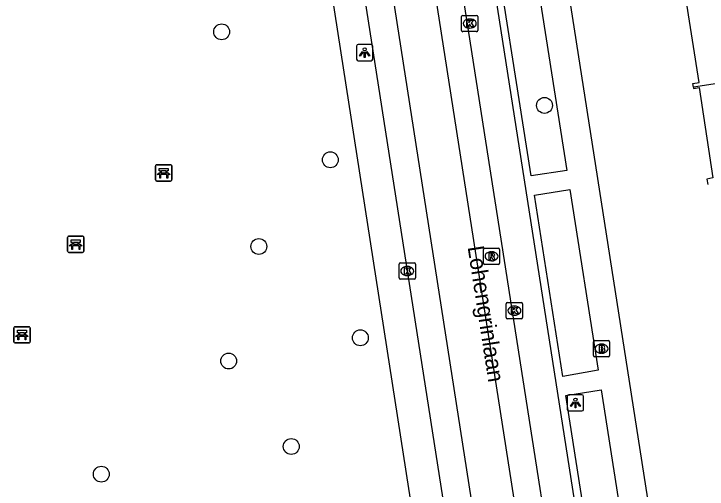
# Model space of a CAD drawing. Extents: x 160077 to 160945, y 386481 to 387498.
# Drawn here: x 160634.83 to 160677.56, y 386939.33 to 386968.61 of the extents above; entities that cross this region are included whole.
import ezdxf

# ---------------------------------------------------------------- set-up
doc = ezdxf.new("R2010")
doc.units = 0
for name, color, linetype in [('IMGEO_Bank', 7, 'Continuous'), ('IMGEO_Boom', 7, 'Continuous'), ('IMGEO_Brandkraan', 7, 'Continuous'), ('IMGEO_Kolk', 7, 'Continuous'), ('IMGEO_Lichtpunt', 7, 'Continuous'), ('IMGEO_Openbare_ruimte_label', 7, 'Continuous'), ('IMGEO_Pand', 7, 'Continuous'), ('IMGEO_Rijbaan_lokaal_gesloten', 7, 'Continuous'), ('IMGEO_Rioolput', 7, 'Continuous'), ('IMGEO_Voetpad_open', 7, 'Continuous')]:
    doc.layers.add(name, color=color, linetype=linetype)

msp = doc.modelspace()

# ---------------------------------------------------------------- linework, layer by layer
at = {"layer": 'IMGEO_Bank'}
for p, q in [((160643.636, 386959.313), (160644.477, 386959.313)), ((160644.477, 386959.313), (160643.636, 386959.313)), ((160643.561, 386958.388), (160643.561, 386959.229)), ((160643.561, 386959.229), (160643.561, 386958.388)), ((160643.87, 386958.819), (160643.87, 386958.925)), ((160643.914, 386958.925), (160643.914, 386958.819)), ((160644.202, 386958.931), (160643.92, 386958.931)), ((160644.208, 386958.819), (160644.208, 386958.925)), ((160644.252, 386958.925), (160644.252, 386958.819)), ((160644.561, 386959.238), (160644.561, 386958.397)), ((160644.561, 386958.397), (160644.561, 386959.238)), ((160644.258, 386958.711), (160643.865, 386958.711)), ((160643.92, 386958.813), (160644.202, 386958.813)), ((160644.486, 386958.313), (160643.645, 386958.313)), ((160643.645, 386958.313), (160644.486, 386958.313)), ((160638.139, 386953.992), (160638.139, 386954.833)), ((160638.139, 386954.833), (160638.139, 386953.992)), ((160638.214, 386954.917), (160639.055, 386954.917)), ((160639.055, 386954.917), (160638.214, 386954.917)), ((160639.139, 386954.842), (160639.139, 386954.001)), ((160639.139, 386954.001), (160639.139, 386954.842)), ((160638.836, 386954.315), (160638.443, 386954.315)), ((160638.448, 386954.423), (160638.448, 386954.529)), ((160638.492, 386954.529), (160638.492, 386954.423)), ((160638.78, 386954.535), (160638.498, 386954.535)), ((160638.498, 386954.417), (160638.78, 386954.417)), ((160638.786, 386954.423), (160638.786, 386954.529)), ((160638.83, 386954.529), (160638.83, 386954.423)), ((160639.064, 386953.917), (160638.223, 386953.917)), ((160638.223, 386953.917), (160639.064, 386953.917)), ((160634.825, 386948.415), (160634.825, 386949.256)), ((160634.825, 386949.256), (160634.825, 386948.415)), ((160634.9, 386949.34), (160635.741, 386949.34)), ((160635.741, 386949.34), (160634.9, 386949.34)), ((160635.825, 386949.265), (160635.825, 386948.424)), ((160635.825, 386948.424), (160635.825, 386949.265)), ((160635.522, 386948.738), (160635.129, 386948.738)), ((160635.134, 386948.846), (160635.134, 386948.952)), ((160635.178, 386948.952), (160635.178, 386948.846)), ((160635.466, 386948.958), (160635.184, 386948.958)), ((160635.184, 386948.84), (160635.466, 386948.84)), ((160635.472, 386948.846), (160635.472, 386948.952)), ((160635.516, 386948.952), (160635.516, 386948.846)), ((160635.75, 386948.34), (160634.909, 386948.34)), ((160634.909, 386948.34), (160635.75, 386948.34))]:
    msp.add_line(p, q, dxfattribs=at)
for points in [[(160643.864, 386958.931), (160643.778, 386958.931), (160643.778, 386959.092), (160644.341, 386959.092), (160644.341, 386958.931), (160644.258, 386958.931)], [(160643.808, 386958.711), (160643.666, 386958.711), (160643.778, 386958.813), (160643.864, 386958.813)], [(160643.858, 386958.704), (160643.858, 386958.497), (160643.815, 386958.497), (160643.815, 386958.704)], [(160644.258, 386958.813), (160644.341, 386958.813), (160644.453, 386958.711), (160644.314, 386958.711)], [(160644.308, 386958.704), (160644.308, 386958.497), (160644.264, 386958.497), (160644.264, 386958.704)], [(160638.442, 386954.535), (160638.356, 386954.535), (160638.356, 386954.696), (160638.919, 386954.696), (160638.919, 386954.535), (160638.836, 386954.535)], [(160638.386, 386954.315), (160638.244, 386954.315), (160638.356, 386954.417), (160638.442, 386954.417)], [(160638.436, 386954.308), (160638.436, 386954.101), (160638.393, 386954.101), (160638.393, 386954.308)], [(160638.836, 386954.417), (160638.919, 386954.417), (160639.031, 386954.315), (160638.892, 386954.315)], [(160638.886, 386954.308), (160638.886, 386954.101), (160638.842, 386954.101), (160638.842, 386954.308)], [(160635.128, 386948.958), (160635.042, 386948.958), (160635.042, 386949.119), (160635.605, 386949.119), (160635.605, 386948.958), (160635.522, 386948.958)], [(160635.072, 386948.738), (160634.93, 386948.738), (160635.042, 386948.84), (160635.128, 386948.84)], [(160635.122, 386948.731), (160635.122, 386948.524), (160635.079, 386948.524), (160635.079, 386948.731)], [(160635.522, 386948.84), (160635.605, 386948.84), (160635.717, 386948.738), (160635.578, 386948.738)], [(160635.572, 386948.731), (160635.572, 386948.524), (160635.528, 386948.524), (160635.528, 386948.731)]]:
    msp.add_lwpolyline(points, dxfattribs=at)
for centre, radius, start, end in [((160643.639, 386959.235), 0.0779, 92.4484, 184.2845), ((160643.639, 386959.235), 0.0779, 92.4484, 184.2845), ((160644.483, 386959.235), 0.0779, 2.4484, 94.2845), ((160644.483, 386959.235), 0.0779, 2.4484, 94.2845), ((160643.863, 386958.924), 0.00671, 2.8957, 87.1043), ((160643.92, 386958.924), 0.00671, 92.8957, 177.1043), ((160644.202, 386958.924), 0.00671, 2.8957, 87.1043), ((160644.259, 386958.924), 0.00671, 92.8957, 177.1043), ((160643.808, 386958.704), 0.00671, 2.8957, 87.1043), ((160643.865, 386958.704), 0.00671, 92.8957, 177.1043), ((160643.863, 386958.82), 0.00671, 272.8957, 357.1043), ((160643.92, 386958.82), 0.00671, 182.8957, 267.1043), ((160644.202, 386958.82), 0.00671, 272.8957, 357.1043), ((160644.259, 386958.82), 0.00671, 182.8957, 267.1043), ((160644.257, 386958.704), 0.00671, 2.8957, 87.1043), ((160644.314, 386958.704), 0.00671, 92.8957, 177.1043), ((160643.639, 386958.391), 0.0779, 182.4484, 274.2845), ((160643.639, 386958.391), 0.0779, 182.4484, 274.2845), ((160644.483, 386958.391), 0.0779, 272.4484, 4.2845), ((160644.483, 386958.391), 0.0779, 272.4484, 4.2845), ((160638.217, 386954.839), 0.0779, 92.4484, 184.2845), ((160638.217, 386954.839), 0.0779, 92.4484, 184.2845), ((160639.061, 386954.839), 0.0779, 2.4484, 94.2845), ((160639.061, 386954.839), 0.0779, 2.4484, 94.2845), ((160638.386, 386954.308), 0.00671, 2.8957, 87.1043), ((160638.443, 386954.308), 0.00671, 92.8957, 177.1043), ((160638.441, 386954.528), 0.00671, 2.8957, 87.1043), ((160638.441, 386954.424), 0.00671, 272.8957, 357.1043), ((160638.498, 386954.528), 0.00671, 92.8957, 177.1043), ((160638.498, 386954.424), 0.00671, 182.8957, 267.1043), ((160638.78, 386954.528), 0.00671, 2.8957, 87.1043), ((160638.78, 386954.424), 0.00671, 272.8957, 357.1043), ((160638.837, 386954.528), 0.00671, 92.8957, 177.1043), ((160638.837, 386954.424), 0.00671, 182.8957, 267.1043), ((160638.835, 386954.308), 0.00671, 2.8957, 87.1043), ((160638.892, 386954.308), 0.00671, 92.8957, 177.1043), ((160638.217, 386953.995), 0.0779, 182.4484, 274.2845), ((160638.217, 386953.995), 0.0779, 182.4484, 274.2845), ((160639.061, 386953.995), 0.0779, 272.4484, 4.2845), ((160639.061, 386953.995), 0.0779, 272.4484, 4.2845), ((160634.903, 386949.262), 0.0779, 92.4484, 184.2845), ((160634.903, 386949.262), 0.0779, 92.4484, 184.2845), ((160635.747, 386949.262), 0.0779, 2.4484, 94.2845), ((160635.747, 386949.262), 0.0779, 2.4484, 94.2845), ((160635.072, 386948.731), 0.00671, 2.8957, 87.1043), ((160635.129, 386948.731), 0.00671, 92.8957, 177.1043), ((160635.127, 386948.951), 0.00671, 2.8957, 87.1043), ((160635.127, 386948.847), 0.00671, 272.8957, 357.1043), ((160635.184, 386948.951), 0.00671, 92.8957, 177.1043), ((160635.184, 386948.847), 0.00671, 182.8957, 267.1043), ((160635.466, 386948.951), 0.00671, 2.8957, 87.1043), ((160635.466, 386948.847), 0.00671, 272.8957, 357.1043), ((160635.523, 386948.951), 0.00671, 92.8957, 177.1043), ((160635.523, 386948.847), 0.00671, 182.8957, 267.1043), ((160635.521, 386948.731), 0.00671, 2.8957, 87.1043), ((160635.578, 386948.731), 0.00671, 92.8957, 177.1043), ((160634.903, 386948.418), 0.0779, 182.4484, 274.2845), ((160634.903, 386948.418), 0.0779, 182.4484, 274.2845), ((160635.747, 386948.418), 0.0779, 272.4484, 4.2845), ((160635.747, 386948.418), 0.0779, 272.4484, 4.2845)]:
    msp.add_arc(centre, radius, start, end, dxfattribs=at)
at = {"layer": 'IMGEO_Boom'}
for centre in [(160647.634, 386967.504), (160667.541, 386962.97), (160654.334, 386959.621), (160649.927, 386954.28), (160656.186, 386948.656), (160648.068, 386947.222), (160651.925, 386941.956), (160640.215, 386940.252)]:
    msp.add_circle(centre, 0.489, dxfattribs=at)
at = {"layer": 'IMGEO_Brandkraan'}
for p, q in [((160670.553, 386947.56), (160670.553, 386948.412)), ((160670.628, 386948.486), (160671.48, 386948.486)), ((160671.041, 386948.266), (160671.066, 386948.266)), ((160671.554, 386948.412), (160671.554, 386947.56)), ((160671.48, 386947.486), (160670.628, 386947.486)), ((160671.064, 386947.706), (160671.039, 386947.706))]:
    msp.add_line(p, q, dxfattribs=at)
for points in [[(160670.553, 386947.56), (160670.553, 386948.412)], [(160670.628, 386948.486), (160671.48, 386948.486)], [(160670.901, 386948.186), (160670.901, 386947.786), (160671.114, 386947.786)], [(160671.132, 386948.186), (160670.901, 386948.186)], [(160671.554, 386948.412), (160671.554, 386947.56)], [(160671.08, 386948.105), (160671.026, 386948.105), (160671.026, 386948.029)], [(160671.026, 386948.029), (160671.079, 386948.029)], [(160671.088, 386947.953), (160671.026, 386947.953), (160671.026, 386947.872)], [(160671.026, 386947.872), (160671.088, 386947.872)], [(160671.48, 386947.486), (160670.628, 386947.486)]]:
    msp.add_lwpolyline(points, dxfattribs=at)
for centre, radius, start, end in [((160670.63, 386948.41), 0.0765, 91.552, 178.448), ((160670.63, 386948.41), 0.0765, 91.552, 178.448), ((160671.136, 386948.041), 0.145, 59.4692, 91.5367), ((160671.161, 386948.088), 0.0922, 285.5137, 58.1501), ((160671.478, 386948.41), 0.0765, 1.552, 88.448), ((160671.478, 386948.41), 0.0765, 1.552, 88.448), ((160671.081, 386948.067), 0.0379, 267.8285, 90.9355), ((160671.089, 386947.912), 0.0404, 269.8759, 90.5077), ((160671.12, 386948.037), 0.251, 268.6676, 293.5347), ((160671.166, 386947.896), 0.105, 301.3115, 78.989), ((160670.63, 386947.562), 0.0765, 181.552, 268.448), ((160670.63, 386947.562), 0.0765, 181.552, 268.448), ((160671.478, 386947.562), 0.0765, 271.552, 358.448), ((160671.478, 386947.562), 0.0765, 271.552, 358.448)]:
    msp.add_arc(centre, radius, start, end, dxfattribs=at)
for centre, major_axis, ratio, start_param, end_param in [((160671.04, 386947.986), (-0.387, 0.002), 0.722429, 4.712389, 7.853982), ((160671.065, 386947.986), (-0.39, 0.002), 0.717154, 1.570796, 4.712389)]:
    msp.add_ellipse(centre, major_axis=major_axis, ratio=ratio, start_param=start_param, end_param=end_param, dxfattribs=at)
at = {"layer": 'IMGEO_Kolk'}
for p, q in [((160662.426, 386967.587), (160662.426, 386968.439)), ((160662.501, 386968.513), (160663.353, 386968.513)), ((160662.914, 386968.293), (160662.939, 386968.293)), ((160663.427, 386968.439), (160663.427, 386967.587)), ((160663.353, 386967.513), (160662.501, 386967.513)), ((160662.937, 386967.733), (160662.912, 386967.733)), ((160658.576, 386952.341), (160658.576, 386953.193)), ((160658.651, 386953.267), (160659.503, 386953.267)), ((160659.064, 386953.047), (160659.089, 386953.047)), ((160659.577, 386953.193), (160659.577, 386952.341)), ((160659.087, 386952.487), (160659.062, 386952.487)), ((160659.503, 386952.267), (160658.651, 386952.267)), ((160665.18, 386949.901), (160665.18, 386950.753)), ((160665.255, 386950.827), (160666.107, 386950.827)), ((160666.181, 386950.753), (160666.181, 386949.901)), ((160665.668, 386950.607), (160665.693, 386950.607)), ((160665.691, 386950.047), (160665.666, 386950.047)), ((160666.107, 386949.827), (160665.255, 386949.827))]:
    msp.add_line(p, q, dxfattribs=at)
for points in [[(160662.426, 386967.587), (160662.426, 386968.439)], [(160662.501, 386968.513), (160663.353, 386968.513)], [(160663.427, 386968.439), (160663.427, 386967.587)], [(160662.747, 386968.213), (160662.87, 386968.213), (160662.87, 386968.062), (160663, 386968.213), (160663.164, 386968.213), (160663.018, 386968.062), (160663.171, 386967.813), (160663.019, 386967.813), (160662.934, 386967.977), (160662.87, 386967.91), (160662.87, 386967.813), (160662.747, 386967.813), (160662.747, 386968.213)], [(160663.353, 386967.513), (160662.501, 386967.513)], [(160658.576, 386952.341), (160658.576, 386953.193)], [(160658.651, 386953.267), (160659.503, 386953.267)], [(160658.897, 386952.967), (160659.02, 386952.967), (160659.02, 386952.816), (160659.15, 386952.967), (160659.314, 386952.967), (160659.168, 386952.816), (160659.321, 386952.567), (160659.169, 386952.567), (160659.084, 386952.731), (160659.02, 386952.664), (160659.02, 386952.567), (160658.897, 386952.567), (160658.897, 386952.967)], [(160659.577, 386953.193), (160659.577, 386952.341)], [(160659.503, 386952.267), (160658.651, 386952.267)], [(160665.18, 386949.901), (160665.18, 386950.753)], [(160665.255, 386950.827), (160666.107, 386950.827)], [(160666.181, 386950.753), (160666.181, 386949.901)], [(160665.501, 386950.527), (160665.624, 386950.527), (160665.624, 386950.376), (160665.754, 386950.527), (160665.918, 386950.527), (160665.772, 386950.376), (160665.925, 386950.127), (160665.773, 386950.127), (160665.688, 386950.291), (160665.624, 386950.224), (160665.624, 386950.127), (160665.501, 386950.127), (160665.501, 386950.527)], [(160666.107, 386949.827), (160665.255, 386949.827)]]:
    msp.add_lwpolyline(points, dxfattribs=at)
for centre, start, end in [((160662.503, 386968.437), 91.552, 178.448), ((160662.503, 386968.437), 91.552, 178.448), ((160663.351, 386968.437), 1.552, 88.448), ((160663.351, 386968.437), 1.552, 88.448), ((160662.503, 386967.589), 181.552, 268.448), ((160662.503, 386967.589), 181.552, 268.448), ((160663.351, 386967.589), 271.552, 358.448), ((160663.351, 386967.589), 271.552, 358.448), ((160658.653, 386953.191), 91.552, 178.448), ((160658.653, 386953.191), 91.552, 178.448), ((160659.501, 386953.191), 1.552, 88.448), ((160659.501, 386953.191), 1.552, 88.448), ((160658.653, 386952.343), 181.552, 268.448), ((160658.653, 386952.343), 181.552, 268.448), ((160659.501, 386952.343), 271.552, 358.448), ((160659.501, 386952.343), 271.552, 358.448), ((160665.257, 386950.751), 91.552, 178.448), ((160665.257, 386950.751), 91.552, 178.448), ((160666.105, 386950.751), 1.552, 88.448), ((160666.105, 386950.751), 1.552, 88.448), ((160665.257, 386949.903), 181.552, 268.448), ((160665.257, 386949.903), 181.552, 268.448), ((160666.105, 386949.903), 271.552, 358.448), ((160666.105, 386949.903), 271.552, 358.448)]:
    msp.add_arc(centre, 0.0765, start, end, dxfattribs=at)
for centre, major_axis, ratio, start_param, end_param in [((160662.913, 386968.013), (-0.387, 0.002), 0.722429, 4.712389, 7.853982), ((160662.938, 386968.013), (-0.39, 0.002), 0.717154, 1.570796, 4.712389), ((160659.063, 386952.767), (-0.387, 0.002), 0.722429, 4.712389, 7.853982), ((160659.088, 386952.767), (-0.39, 0.002), 0.717154, 1.570796, 4.712389), ((160665.667, 386950.327), (-0.387, 0.002), 0.722429, 4.712389, 7.853982), ((160665.692, 386950.327), (-0.39, 0.002), 0.717154, 1.570796, 4.712389)]:
    msp.add_ellipse(centre, major_axis=major_axis, ratio=ratio, start_param=start_param, end_param=end_param, dxfattribs=at)
at = {"layer": 'IMGEO_Lichtpunt'}
for p, q in [((160655.953, 386966.627), (160655.953, 386965.82)), ((160655.953, 386966.627), (160655.953, 386965.82)), ((160656.855, 386966.722), (160656.047, 386966.722)), ((160656.855, 386966.722), (160656.047, 386966.722)), ((160656.949, 386965.82), (160656.949, 386966.627)), ((160656.949, 386965.82), (160656.949, 386966.627)), ((160656.047, 386965.726), (160656.855, 386965.726)), ((160656.047, 386965.726), (160656.855, 386965.726)), ((160668.944, 386945.047), (160668.944, 386944.24)), ((160668.944, 386945.047), (160668.944, 386944.24)), ((160669.846, 386945.142), (160669.038, 386945.142)), ((160669.846, 386945.142), (160669.038, 386945.142)), ((160669.94, 386944.24), (160669.94, 386945.047)), ((160669.94, 386944.24), (160669.94, 386945.047)), ((160669.038, 386944.146), (160669.846, 386944.146)), ((160669.038, 386944.146), (160669.846, 386944.146))]:
    msp.add_line(p, q, dxfattribs=at)
for points in [[(160656.327, 386966.291), (160656.366, 386966.263), (160656.178, 386966.001), (160656.14, 386966.028), (160656.327, 386966.291)], [(160656.429, 386966.243), (160656.476, 386966.243), (160656.476, 386965.921), (160656.429, 386965.921), (160656.429, 386966.243)], [(160656.539, 386966.263), (160656.577, 386966.29), (160656.764, 386966.028), (160656.725, 386966), (160656.539, 386966.263)], [(160669.318, 386944.711), (160669.357, 386944.683), (160669.169, 386944.421), (160669.131, 386944.448), (160669.318, 386944.711)], [(160669.42, 386944.663), (160669.467, 386944.663), (160669.467, 386944.341), (160669.42, 386944.341), (160669.42, 386944.663)], [(160669.53, 386944.683), (160669.568, 386944.71), (160669.755, 386944.448), (160669.716, 386944.42), (160669.53, 386944.683)]]:
    msp.add_lwpolyline(points, dxfattribs=at)
for centre in [(160656.452, 386966.425), (160669.443, 386944.845)]:
    msp.add_circle(centre, 0.0994, dxfattribs=at)
for centre, start, end in [((160656.047, 386966.627), 90, 180), ((160656.047, 386966.627), 90, 180), ((160656.855, 386966.627), 0, 90), ((160656.855, 386966.627), 0, 90), ((160656.047, 386965.82), 180, 270), ((160656.047, 386965.82), 180, 270), ((160656.855, 386965.82), 270, 0), ((160656.855, 386965.82), 270, 360), ((160669.038, 386945.047), 90, 180), ((160669.038, 386945.047), 90, 180), ((160669.846, 386945.047), 0, 90), ((160669.846, 386945.047), 0, 90), ((160669.038, 386944.24), 180, 270), ((160669.038, 386944.24), 180, 270), ((160669.846, 386944.24), 270, 0), ((160669.846, 386944.24), 270, 360)]:
    msp.add_arc(centre, 0.0946, start, end, dxfattribs=at)
at = {"layer": 'IMGEO_Pand'}
for points in [[(160676.713, 386964.086), (160676.676, 386964.321), (160677.076, 386964.384), (160676.195, 386970.004), (160675.833, 386969.948), (160675.814, 386970.073)], [(160684.479, 386965.272), (160683.56, 386965.132), (160676.713, 386964.086)], [(160676.713, 386964.086), (160676.724, 386964.014), (160677.072, 386964.069), (160677.922, 386958.5), (160677.548, 386958.429), (160677.61, 386958.098)]]:
    msp.add_lwpolyline(points, dxfattribs=at)
at = {"layer": 'IMGEO_Rijbaan_lokaal_gesloten'}
for points in [[(160648.402, 387049.206), (160672.534, 386894.617)], [(160645.848, 387048.796), (160669.948, 386894.233)], [(160647.235, 387028.489), (160647.328, 387027.89), (160662.549, 386930.569), (160663.045, 386927.404)], [(160653.752, 387025.629), (160670.124, 386921.003), (160671.293, 386913.55)]]:
    msp.add_lwpolyline(points, dxfattribs=at)
at = {"layer": 'IMGEO_Rioolput'}
for p, q in [((160663.846, 386954.176), (160664.698, 386954.176)), ((160663.771, 386953.25), (160663.771, 386954.102)), ((160664.259, 386953.956), (160664.284, 386953.956)), ((160664.772, 386954.102), (160664.772, 386953.25)), ((160664.282, 386953.396), (160664.257, 386953.396)), ((160664.698, 386953.176), (160663.846, 386953.176))]:
    msp.add_line(p, q, dxfattribs=at)
for points in [[(160663.846, 386954.176), (160664.698, 386954.176)], [(160663.771, 386953.25), (160663.771, 386954.102)], [(160664.36, 386953.874), (160664.108, 386953.876), (160664.108, 386953.476)], [(160664.286, 386953.795), (160664.232, 386953.795), (160664.232, 386953.714)], [(160664.232, 386953.714), (160664.284, 386953.714)], [(160664.772, 386954.102), (160664.772, 386953.25)], [(160664.108, 386953.476), (160664.232, 386953.476), (160664.232, 386953.638), (160664.243, 386953.638)], [(160664.29, 386953.609), (160664.361, 386953.476), (160664.501, 386953.476), (160664.436, 386953.602)], [(160664.698, 386953.176), (160663.846, 386953.176)]]:
    msp.add_lwpolyline(points, dxfattribs=at)
for centre, radius, start, end in [((160663.848, 386954.1), 0.0765, 91.552, 178.448), ((160663.848, 386954.1), 0.0765, 91.552, 178.448), ((160664.696, 386954.1), 0.0765, 1.552, 88.448), ((160664.696, 386954.1), 0.0765, 1.552, 88.448), ((160664.268, 386953.903), 0.19, 274.7715, 282.9687), ((160664.292, 386953.699), 0.0964, 77.0061, 93.1865), ((160664.306, 386953.756), 0.0378, 276.6634, 79.6772), ((160664.359, 386953.764), 0.109, 350.3612, 89.416), ((160664.357, 386953.764), 0.112, 277.5842, 350.9817), ((160664.242, 386953.585), 0.0533, 26.0293, 88.6989), ((160664.341, 386953.549), 0.108, 29.5134, 73.7905), ((160663.848, 386953.252), 0.0765, 181.552, 268.448), ((160663.848, 386953.252), 0.0765, 181.552, 268.448), ((160664.696, 386953.252), 0.0765, 271.552, 358.448), ((160664.696, 386953.252), 0.0765, 271.552, 358.448)]:
    msp.add_arc(centre, radius, start, end, dxfattribs=at)
for centre, major_axis, ratio, start_param, end_param in [((160664.258, 386953.676), (-0.387, 0.002), 0.722429, 4.712389, 7.853982), ((160664.283, 386953.676), (-0.39, 0.002), 0.717154, 1.570796, 4.712389)]:
    msp.add_ellipse(centre, major_axis=major_axis, ratio=ratio, start_param=start_param, end_param=end_param, dxfattribs=at)
at = {"layer": 'IMGEO_Voetpad_open'}
for points in [[(160677.601, 386915.063), (160660.76, 387022.948)], [(160656.203, 387022.932), (160671.24, 386926.7), (160672.81, 386916.832)], [(160659.613, 386936.631), (160659.595, 386936.766), (160659.182, 386939.374), (160649.771, 386999.952)], [(160664.112, 386975.246), (160666.313, 386975.599), (160668.911, 386958.97), (160666.722, 386958.637), (160664.112, 386975.246)], [(160666.914, 386957.438), (160669.096, 386957.785), (160670.836, 386946.656), (160668.664, 386946.279), (160666.914, 386957.438)], [(160668.851, 386945.095), (160671.04, 386945.459), (160673.473, 386929.827), (160671.298, 386929.488), (160668.851, 386945.095)]]:
    msp.add_lwpolyline(points, dxfattribs=at)

# ---------------------------------------------------------------- texts
at = {"layer": 'IMGEO_Openbare_ruimte_label'}
msp.add_text('Lohengrinlaan', height=1, rotation=278.7462, dxfattribs=at).set_placement((160662.795, 386954.247))

doc.saveas('drawing.dxf')
